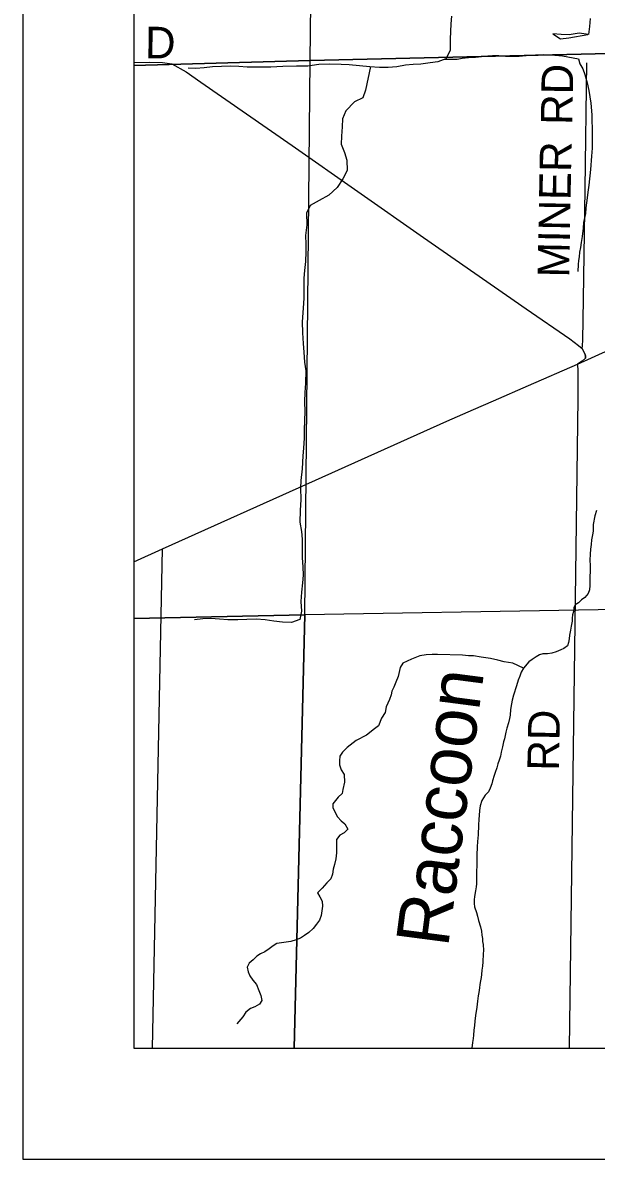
# Model space of a CAD drawing. Extents: x 0 to 34, y 0 to 22.
# Drawn here: x 2 to 2.516, y 14 to 15.023 of the extents above; entities that cross this region are included whole.
import ezdxf

# ---------------------------------------------------------------- set-up
doc = ezdxf.new("R2010")
doc.units = 0
for name, color, linetype in [('GM_X_Corporation', 7, 'Continuous'), ('GM_X_County_Road', 7, 'Continuous'), ('GM_X_County_Road_Text', 7, 'Continuous'), ('GM_X_Minor_River', 7, 'Continuous'), ('GM_X_Minor_River_Text', 7, 'Continuous'), ('GM_X_Township_Road', 7, 'Continuous'), ('GM_X_Township_Road_Text', 7, 'Continuous'), ('GM_X_US_Route', 7, 'Continuous'), ('SH_Data', 7, 'Continuous')]:
    doc.layers.add(name, color=color, linetype=linetype)

msp = doc.modelspace()

# ---------------------------------------------------------------- linework, layer by layer
at = {"layer": 'GM_X_Corporation'}
for points in [[(2.1, 15.8632), (2.1, 14.1), (6.0569, 14.1)], [(2.1, 15.8632), (2.1, 14.1), (3.2397, 14.1)]]:
    msp.add_lwpolyline(points, dxfattribs=at)
for points in [[(2.7675, 15.4363), (2.7592, 15.0012), (2.2588, 14.9895), (2.2639, 15.4258), (2.2753, 15.4255)], [(2.1, 15.4269), (2.1, 14.9848), (2.2588, 14.9895), (2.2639, 15.4258)], [(2.7592, 15.0012), (2.7465, 14.4988), (2.2539, 14.4902), (2.2588, 14.9895)], [(2.1, 14.9848), (2.1, 14.487), (2.2539, 14.4902), (2.2588, 14.9895)], [(2.2443, 14.1), (2.7393, 14.1), (2.7465, 14.4988), (2.2539, 14.4902)], [(2.1, 14.487), (2.1, 14.1), (2.2443, 14.1), (2.2539, 14.4902)]]:
    msp.add_lwpolyline(points, close=True, dxfattribs=at)
at = {"layer": 'GM_X_County_Road'}
for points in [[(2.1, 14.9876), (2.1139, 14.9879), (2.1258, 14.9878), (2.1343, 14.9865), (2.1472, 14.9792), (2.1603, 14.97), (2.2424, 14.9129), (2.3608, 14.83), (2.4531, 14.7659), (2.4924, 14.7387), (2.5002, 14.7329), (2.5036, 14.7301)], [(2.5036, 14.7301), (2.5062, 14.7248), (2.5067, 14.7231), (2.5066, 14.7218)], [(2.5066, 14.7218), (2.5066, 14.7214), (2.5037, 14.7188), (2.4995, 14.7159)]]:
    msp.add_lwpolyline(points, dxfattribs=at)
at = {"layer": 'GM_X_Minor_River'}
for points in [[(2.3859, 15.0293), (2.3853, 15.0225), (2.3849, 15.0157), (2.3847, 15.0088), (2.3846, 14.9984), (2.3808, 14.9909), (2.3737, 14.9883), (2.3667, 14.9873), (2.3583, 14.9862), (2.3514, 14.9859), (2.3444, 14.9851), (2.3367, 14.9838), (2.3288, 14.9831), (2.321, 14.9831), (2.3124, 14.9838), (2.303, 14.9846), (2.2937, 14.9854), (2.2867, 14.9858), (2.2759, 14.986), (2.2664, 14.9857), (2.2566, 14.9844), (2.2464, 14.9842), (2.234, 14.9839), (2.2234, 14.9835), (2.2101, 14.9833), (2.2019, 14.9833), (2.1944, 14.9839), (2.1872, 14.9843), (2.1788, 14.984), (2.1708, 14.9837), (2.1632, 14.9829), (2.1558, 14.9822), (2.1488, 14.9824)], [(2.5107, 15.0274), (2.5103, 15.02), (2.5094, 15.013), (2.5009, 15.0142), (2.4919, 15.0126), (2.4845, 15.0128), (2.4771, 15.0134), (2.484, 15.009), (2.4914, 15.0098), (2.5088, 15.0129)], [(2.38, 14.9906), (2.3909, 14.9908), (2.3956, 14.9916), (2.4013, 14.9922), (2.4074, 14.9926), (2.4185, 14.9938), (2.4227, 14.9941), (2.4284, 14.9941), (2.4346, 14.9935), (2.4405, 14.9934), (2.4467, 14.9934), (2.4532, 14.994), (2.4572, 14.9944), (2.4616, 14.9945), (2.469, 14.9948), (2.473, 14.9947), (2.479, 14.9944), (2.4857, 14.9938), (2.4906, 14.9929), (2.4955, 14.9918), (2.5004, 14.9909), (2.5014, 14.9863), (2.5041, 14.9819), (2.5061, 14.9769), (2.5081, 14.9692), (2.5095, 14.9623), (2.5104, 14.9566), (2.5114, 14.9511), (2.5123, 14.9406), (2.5124, 14.9339), (2.5127, 14.9296), (2.5125, 14.924), (2.5125, 14.9172), (2.5125, 14.9106), (2.5121, 14.9032), (2.5112, 14.8914), (2.5097, 14.8772), (2.5088, 14.871), (2.5082, 14.8657), (2.507, 14.8568), (2.5065, 14.8518), (2.5049, 14.8437), (2.5046, 14.8386), (2.5036, 14.831), (2.5027, 14.8255), (2.502, 14.821), (2.5013, 14.817), (2.5008, 14.8127), (2.5004, 14.8093), (2.5001, 14.8057), (2.4997, 14.7994)], [(2.3131, 14.984), (2.3086, 14.9628), (2.3061, 14.9558), (2.2986, 14.9521), (2.2908, 14.9441), (2.2878, 14.9368), (2.2874, 14.9298), (2.2869, 14.9214), (2.2867, 14.9142), (2.2896, 14.9065), (2.2918, 14.8996), (2.2919, 14.8903), (2.2881, 14.8828), (2.2831, 14.875), (2.2754, 14.8682), (2.2669, 14.8635), (2.2588, 14.859), (2.2555, 14.8519), (2.2556, 14.8414), (2.2544, 14.8319), (2.2549, 14.8241), (2.2549, 14.8173), (2.2545, 14.8084), (2.2537, 14.8002), (2.2531, 14.7934), (2.2531, 14.7852), (2.253, 14.7754), (2.2523, 14.7665), (2.2514, 14.7541), (2.2519, 14.7441), (2.2524, 14.7347), (2.2529, 14.7267), (2.2536, 14.7178), (2.2547, 14.71), (2.2544, 14.699), (2.254, 14.6904), (2.2537, 14.6823), (2.2539, 14.6731), (2.2535, 14.6656), (2.2534, 14.6564), (2.2534, 14.6494), (2.2527, 14.6403), (2.2522, 14.6333), (2.2516, 14.6217), (2.2502, 14.6111), (2.25, 14.6043), (2.2503, 14.5942), (2.2496, 14.5842), (2.2495, 14.5737), (2.251, 14.5653), (2.2514, 14.5585), (2.2515, 14.5501), (2.2516, 14.5416), (2.252, 14.5334), (2.2525, 14.526), (2.2517, 14.5191), (2.2509, 14.5106), (2.2503, 14.5023), (2.251, 14.4937), (2.2495, 14.4862), (2.242, 14.4833), (2.2338, 14.4838), (2.2261, 14.4847), (2.2181, 14.4857), (2.21, 14.4863), (2.2016, 14.4862), (2.1937, 14.4859), (2.1847, 14.4857), (2.177, 14.4863), (2.1694, 14.4869), (2.162, 14.4866), (2.1546, 14.4858)], [(2.5164, 14.5841), (2.5149, 14.5793), (2.5134, 14.5717), (2.5134, 14.5657), (2.5129, 14.5622), (2.5121, 14.5579), (2.5116, 14.5535), (2.511, 14.5493), (2.5107, 14.5449), (2.5105, 14.5396), (2.5107, 14.5347), (2.5108, 14.5296), (2.5106, 14.5244), (2.5106, 14.5195), (2.5104, 14.5168), (2.5101, 14.5127), (2.509, 14.5096), (2.5061, 14.506), (2.5031, 14.5037), (2.5003, 14.5012), (2.4972, 14.4993), (2.4961, 14.4967), (2.4958, 14.4934), (2.495, 14.4904), (2.4946, 14.4873), (2.4945, 14.4845), (2.4937, 14.4801), (2.493, 14.4765), (2.4923, 14.4721), (2.4917, 14.4687), (2.4912, 14.4655), (2.4902, 14.4624), (2.487, 14.46), (2.4842, 14.4588), (2.4802, 14.4571), (2.4762, 14.4557), (2.4722, 14.4552), (2.468, 14.455), (2.465, 14.4542), (2.462, 14.4525), (2.4586, 14.45), (2.4556, 14.4479), (2.4507, 14.4422), (2.4486, 14.4387), (2.4475, 14.4351), (2.4458, 14.4315), (2.4443, 14.4264), (2.4435, 14.4237), (2.4426, 14.4207), (2.4417, 14.418), (2.4404, 14.4133), (2.44, 14.4102), (2.4391, 14.4049), (2.4387, 14.3998), (2.438, 14.3969), (2.4372, 14.3931), (2.4357, 14.3882), (2.4348, 14.3847), (2.4343, 14.3815), (2.4335, 14.3787), (2.4328, 14.376), (2.4317, 14.3713), (2.4307, 14.3665), (2.43, 14.3631), (2.4287, 14.3593), (2.4277, 14.356), (2.4266, 14.3526), (2.4251, 14.3482), (2.4244, 14.3456), (2.4229, 14.3408)], [(2.4507, 14.4421), (2.4412, 14.4466), (2.4333, 14.4478), (2.4276, 14.4493), (2.4209, 14.4508), (2.4125, 14.452), (2.4057, 14.4532), (2.4012, 14.4533), (2.3957, 14.4538), (2.3733, 14.4545), (2.3684, 14.4544), (2.3632, 14.4542), (2.3573, 14.4532), (2.3498, 14.4502), (2.3421, 14.4468), (2.3398, 14.4429), (2.3378, 14.4348), (2.3358, 14.4295), (2.3339, 14.425), (2.3321, 14.4215), (2.3316, 14.4181), (2.33, 14.4139), (2.3272, 14.4075), (2.3263, 14.4024), (2.3229, 14.3972), (2.3202, 14.3903), (2.3167, 14.3877), (2.3093, 14.3818), (2.3001, 14.377), (2.2921, 14.3709), (2.2878, 14.3667), (2.2853, 14.363), (2.285, 14.3588), (2.285, 14.3552), (2.2866, 14.3506), (2.2894, 14.3465), (2.2895, 14.3395), (2.288, 14.3329), (2.2875, 14.3293), (2.2838, 14.326), (2.2791, 14.3202), (2.2792, 14.3168), (2.2815, 14.3118), (2.2833, 14.3083), (2.2865, 14.3048), (2.2898, 14.3022), (2.2925, 14.2974), (2.2892, 14.2941), (2.2853, 14.2919), (2.2824, 14.288), (2.2823, 14.2846), (2.2825, 14.2795), (2.2824, 14.276), (2.2817, 14.2706), (2.2806, 14.2653), (2.2795, 14.2611), (2.2788, 14.2566), (2.2772, 14.2526), (2.2737, 14.2489), (2.2694, 14.2441), (2.2654, 14.2399), (2.2674, 14.2362), (2.2696, 14.2325), (2.2698, 14.228), (2.2685, 14.2196), (2.2672, 14.2153), (2.2643, 14.2118), (2.2615, 14.2077), (2.2574, 14.2042), (2.2537, 14.2015), (2.25, 14.1991), (2.246, 14.1977), (2.2414, 14.1961), (2.237, 14.1955), (2.2328, 14.195), (2.2288, 14.1942), (2.2254, 14.1922), (2.2217, 14.1895), (2.218, 14.1869), (2.2141, 14.1849), (2.2107, 14.1829), (2.2073, 14.1796), (2.2038, 14.1767), (2.202, 14.1729), (2.203, 14.1687), (2.2045, 14.1651), (2.207, 14.1614), (2.2105, 14.1575), (2.2126, 14.1521), (2.2142, 14.1475), (2.2152, 14.1431), (2.213, 14.1396), (2.209, 14.1372), (2.205, 14.1358), (2.2009, 14.1325), (2.1981, 14.1282), (2.1928, 14.1221)], [(2.4229, 14.3408), (2.4221, 14.3382), (2.4206, 14.3342), (2.4191, 14.3309), (2.4163, 14.3279), (2.4131, 14.3231), (2.4116, 14.3184), (2.4111, 14.314), (2.4107, 14.3096), (2.4105, 14.3062), (2.4102, 14.3009), (2.4102, 14.2979), (2.41, 14.2952), (2.4099, 14.2922), (2.4095, 14.2893), (2.4093, 14.2863), (2.4091, 14.2815), (2.4088, 14.2739), (2.4088, 14.2667), (2.4087, 14.2635), (2.4085, 14.2601), (2.4083, 14.2572), (2.4084, 14.2479), (2.408, 14.2453), (2.4074, 14.2418), (2.4067, 14.2365), (2.4064, 14.2335), (2.4062, 14.2302), (2.4066, 14.2274), (2.4085, 14.2221), (2.4093, 14.2189), (2.4101, 14.2151), (2.412, 14.2094), (2.4128, 14.2054), (2.4133, 14.2018), (2.4137, 14.1989), (2.4139, 14.1961), (2.4143, 14.1934), (2.4146, 14.1881), (2.4144, 14.1849), (2.414, 14.1777), (2.4137, 14.1739), (2.4133, 14.1703), (2.413, 14.1665), (2.4126, 14.1636), (2.412, 14.1608), (2.4115, 14.1575), (2.4111, 14.1545), (2.4104, 14.1501), (2.41, 14.1473), (2.4093, 14.1423), (2.4091, 14.1397), (2.4087, 14.137), (2.4076, 14.1294), (2.4069, 14.1245), (2.4065, 14.1205), (2.406, 14.1163), (2.4056, 14.1119), (2.4053, 14.1089), (2.4047, 14.1051), (2.4043, 14.1)]]:
    msp.add_lwpolyline(points, dxfattribs=at)
at = {"layer": 'GM_X_Township_Road'}
msp.add_line((2.1167, 14.1), (2.1258, 14.5497), dxfattribs=at)
for points in [[(2.5036, 14.7301), (2.504, 14.7328), (2.5042, 14.7376), (2.5048, 14.7745), (2.5062, 14.874), (2.5078, 14.9873)], [(2.5066, 14.7218), (2.5067, 14.7231), (2.5062, 14.7248), (2.5036, 14.7301)], [(2.4995, 14.7159), (2.5037, 14.7188), (2.5066, 14.7214), (2.5066, 14.7218)], [(2.492, 14.1), (2.5, 14.6852), (2.5, 14.7118), (2.4995, 14.7159)]]:
    msp.add_lwpolyline(points, dxfattribs=at)
at = {"layer": 'GM_X_US_Route'}
msp.add_line((2.4058, 14.6752), (2.4236, 14.683), dxfattribs=at)
for points in [[(2.4236, 14.683), (2.4552, 14.6969), (2.4995, 14.7159), (2.5278, 14.7288), (2.5399, 14.7337), (2.5512, 14.7375), (2.5659, 14.7417), (2.5795, 14.7445), (2.5936, 14.7465), (2.608, 14.7475), (2.6114, 14.7476)], [(2.1, 14.5379), (2.1258, 14.5497), (2.2634, 14.6115), (2.3817, 14.6647), (2.4058, 14.6752)]]:
    msp.add_lwpolyline(points, dxfattribs=at)
at = {"layer": 'SH_Data'}
for p, q in [((2, 21), (2, 14)), ((2, 21), (2, 14)), ((2.1, 20.9), (2.1, 14.1)), ((2.1, 20.9), (2.1, 14.1)), ((2.1, 14.1), (8.9, 14.1)), ((2.1, 14.1), (2.1, 14.1)), ((2.1, 14.1), (8.9, 14.1)), ((2, 14), (9, 14)), ((2, 14), (9, 14))]:
    msp.add_line(p, q, dxfattribs=at)

# ---------------------------------------------------------------- texts
at = {"layer": 'GM_X_County_Road_Text'}
msp.add_text('D', height=0.0284, rotation=359.4463, dxfattribs=at).set_placement((2.11, 14.9915))
at = {"layer": 'GM_X_Minor_River_Text'}
msp.add_text('Raccoon', height=0.04738, rotation=82.5483, dxfattribs=at).set_placement((2.3828, 14.1902))
at = {"layer": 'GM_X_Township_Road_Text'}
for s, rotation, p in [('RD', 89.0128, (2.4947, 14.9313)), ('MINER', 88.9357, (2.4918, 14.7939)), ('RD', 89.0128, (2.4826, 14.3497))]:
    msp.add_text(s, height=0.02841, rotation=rotation, dxfattribs=at).set_placement(p)

doc.saveas('drawing.dxf')
